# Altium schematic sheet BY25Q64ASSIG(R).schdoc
size 127 x 101 mm
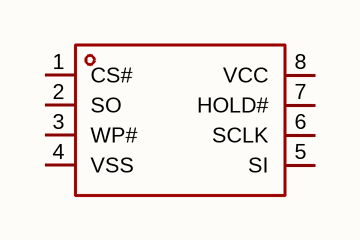
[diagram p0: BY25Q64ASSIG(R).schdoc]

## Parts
U?  by25q64assig(r)  [SOIC-8_L5.2-W5.2-P1.27-LS7.9-BL]  (value not drawn)

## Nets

Not connected (* = marked no-connect by the designer): U? 1(CS#) 2(SO) 3(WP#) 4(VSS) 5(SI) 6(SCLK) 7(HOLD#) 8(VCC)

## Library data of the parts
U? = by25q64assig(r): 接口类型:SPI;存储容量:64Mbit;时钟频率(fc):108MHz;; Manufacturer: BOYAMICRO(博雅); AddInBom: yes; ModelId: 8c61fd1fdc8f4768a544c9969af5a418; ModelTransform: 205.905,311.023,0,0,0,0,0,0,0; Interface: SPI; Memory Size: 64Mbit; Clock Frequency: 108MHz; Voltage - Supply: 2.7V~3.6V; Standby Supply Current: 5uA; Program / Erase Cycles: 100000次; Page Programming Time (Tpp): 600us; Data Retention - TDR (Year): 20年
